(* Logix 5000 project; controller segFORCE_EIP_V1_0 vendor 1 type 14 code 87 rev 20.12; software revision 20.04 *)

TASK MainTask (continuous, watchdog 500 ms) : MainProgram

MODULES
   Controller : vendor 1 type 14 code 87 (CompactLogixL23E_QB1_Controller 0, rev 20.12)
      LocalENB : vendor 1 type 12 code 190 (CompactLogixL23E_QB1_Ethernet 1, Ethernet 192.168.10.88, rev 20.11)
         segFORCE : vendor 1219 type 43 code 100 (Ethernet 192.168.10.82, rev 1.1, StandardDataDriven RPI 2 ms)
      Local : CompactBus (CompactVirtualAdapter 3, rev 20.11)
         Discrete_Inputs : vendor 1 type 7 code 320 (Compact 1, rev 3.1, Input RPI 20 ms)
         Discrete_Outputs : vendor 1 type 7 code 322 (Compact 2, rev 3.1, Output RPI 20 ms)
END_MODULES

TYPE Segment_Status :
STRUCT
   Speed_pulse_status : BOOL;
   Exists : BOOL;
   Group_number : INT;
END_STRUCT
END_TYPE

VAR_GLOBAL   (* controller tags *)
   Group_Mode : DINT;
   msg_Group : MESSAGE;
        MessageParameters(ServiceCode := 16#0010, LocalElement := Group_Mode, ...)
   Status_of_Segments : Segment_Status[50]; {access Read Only}
   Trigger_Group_Write : DINT;
END_VAR

PROGRAM MainProgram   (* main routine MainRoutine *)
VAR
   TempGroupNum : INT;
   TempSegStatus : Segment_Status;
   TempStatusPos : INT;
END_VAR

ROUTINE MainRoutine   (* ladder *)
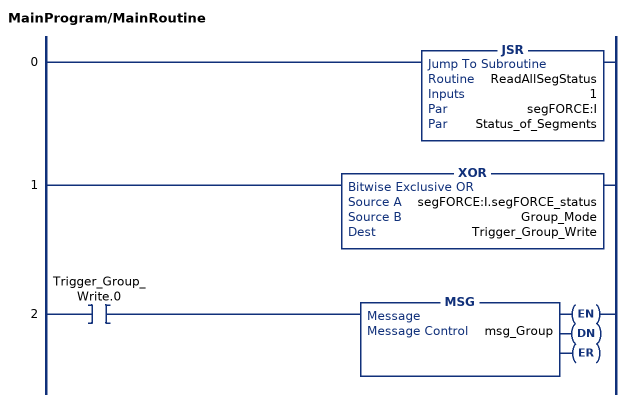
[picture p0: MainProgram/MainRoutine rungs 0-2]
   0: JSR(ReadAllSegStatus,1,segFORCE:I,Status_of_Segments);
   1: XOR(segFORCE:I.segFORCE_status,Group_Mode,Trigger_Group_Write);
   2: XIC(Trigger_Group_Write.0)MSG(msg_Group);
END_ROUTINE

ROUTINE ReadAllSegStatus   (* ladder *)
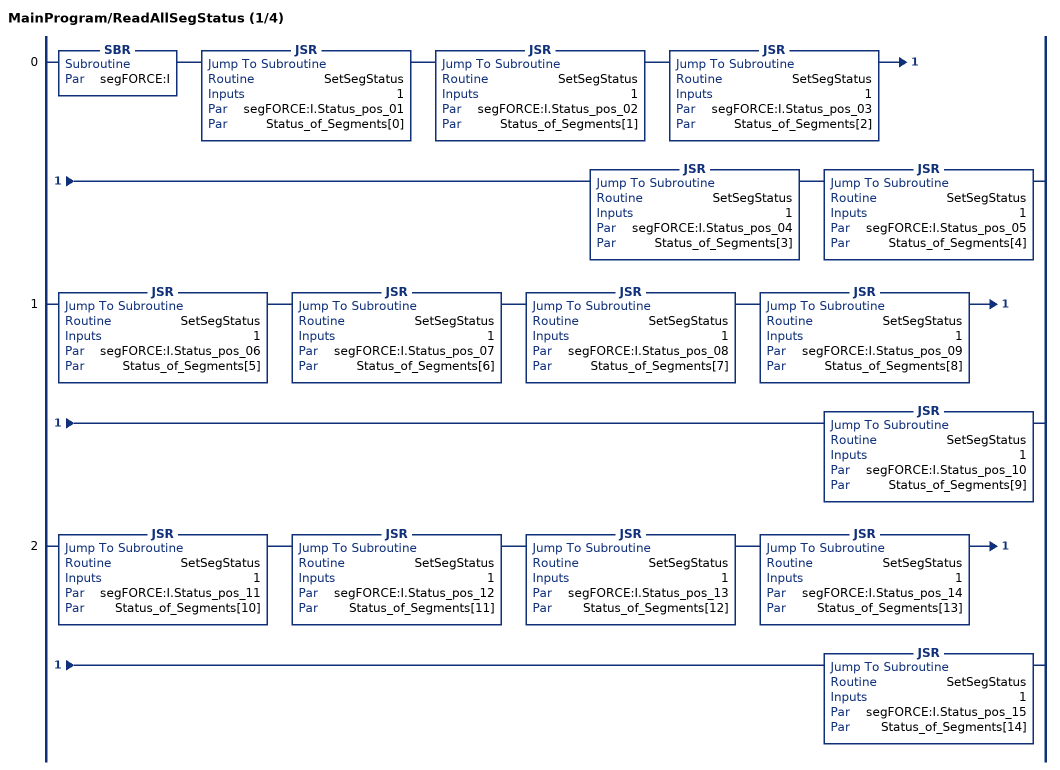
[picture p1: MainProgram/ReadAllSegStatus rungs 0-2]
   0: SBR(segFORCE:I)JSR(SetSegStatus,1,segFORCE:I.Status_pos_01,Status_of_Segments[0])JSR(SetSegStatus,1,segFORCE:I.Status_pos_02,Status_of_Segments[1])JSR(SetSegStatus,1,segFORCE:I.Status_pos_03,Status_of_Segments[2])JSR(SetSegStatus,1,segFORCE:I.Status_pos_04,Status_of_Segments[3])JSR(SetSegStatus,1,segFORCE:I.Status_pos_05,Status_of_Segments[4]);
   1: JSR(SetSegStatus,1,segFORCE:I.Status_pos_06,Status_of_Segments[5])JSR(SetSegStatus,1,segFORCE:I.Status_pos_07,Status_of_Segments[6])JSR(SetSegStatus,1,segFORCE:I.Status_pos_08,Status_of_Segments[7])JSR(SetSegStatus,1,segFORCE:I.Status_pos_09,Status_of_Segments[8])JSR(SetSegStatus,1,segFORCE:I.Status_pos_10,Status_of_Segments[9]);
   2: JSR(SetSegStatus,1,segFORCE:I.Status_pos_11,Status_of_Segments[10])JSR(SetSegStatus,1,segFORCE:I.Status_pos_12,Status_of_Segments[11])JSR(SetSegStatus,1,segFORCE:I.Status_pos_13,Status_of_Segments[12])JSR(SetSegStatus,1,segFORCE:I.Status_pos_14,Status_of_Segments[13])JSR(SetSegStatus,1,segFORCE:I.Status_pos_15,Status_of_Segments[14]);
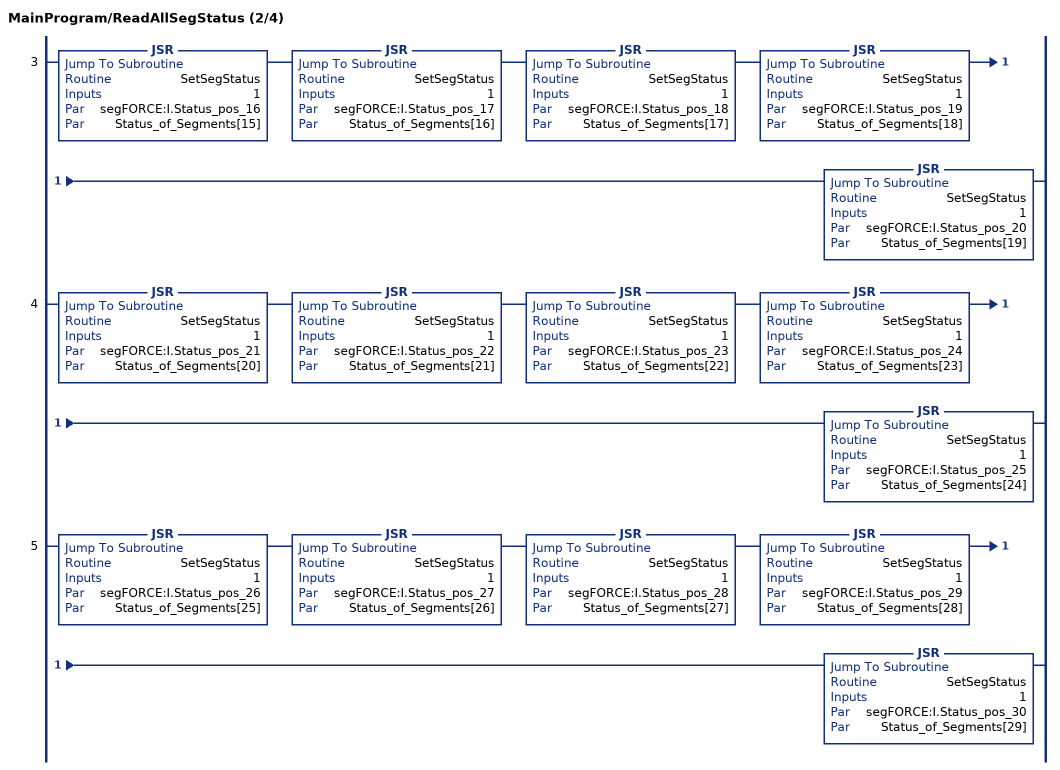
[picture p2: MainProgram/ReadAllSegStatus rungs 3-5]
   3: JSR(SetSegStatus,1,segFORCE:I.Status_pos_16,Status_of_Segments[15])JSR(SetSegStatus,1,segFORCE:I.Status_pos_17,Status_of_Segments[16])JSR(SetSegStatus,1,segFORCE:I.Status_pos_18,Status_of_Segments[17])JSR(SetSegStatus,1,segFORCE:I.Status_pos_19,Status_of_Segments[18])JSR(SetSegStatus,1,segFORCE:I.Status_pos_20,Status_of_Segments[19]);
   4: JSR(SetSegStatus,1,segFORCE:I.Status_pos_21,Status_of_Segments[20])JSR(SetSegStatus,1,segFORCE:I.Status_pos_22,Status_of_Segments[21])JSR(SetSegStatus,1,segFORCE:I.Status_pos_23,Status_of_Segments[22])JSR(SetSegStatus,1,segFORCE:I.Status_pos_24,Status_of_Segments[23])JSR(SetSegStatus,1,segFORCE:I.Status_pos_25,Status_of_Segments[24]);
   5: JSR(SetSegStatus,1,segFORCE:I.Status_pos_26,Status_of_Segments[25])JSR(SetSegStatus,1,segFORCE:I.Status_pos_27,Status_of_Segments[26])JSR(SetSegStatus,1,segFORCE:I.Status_pos_28,Status_of_Segments[27])JSR(SetSegStatus,1,segFORCE:I.Status_pos_29,Status_of_Segments[28])JSR(SetSegStatus,1,segFORCE:I.Status_pos_30,Status_of_Segments[29]);
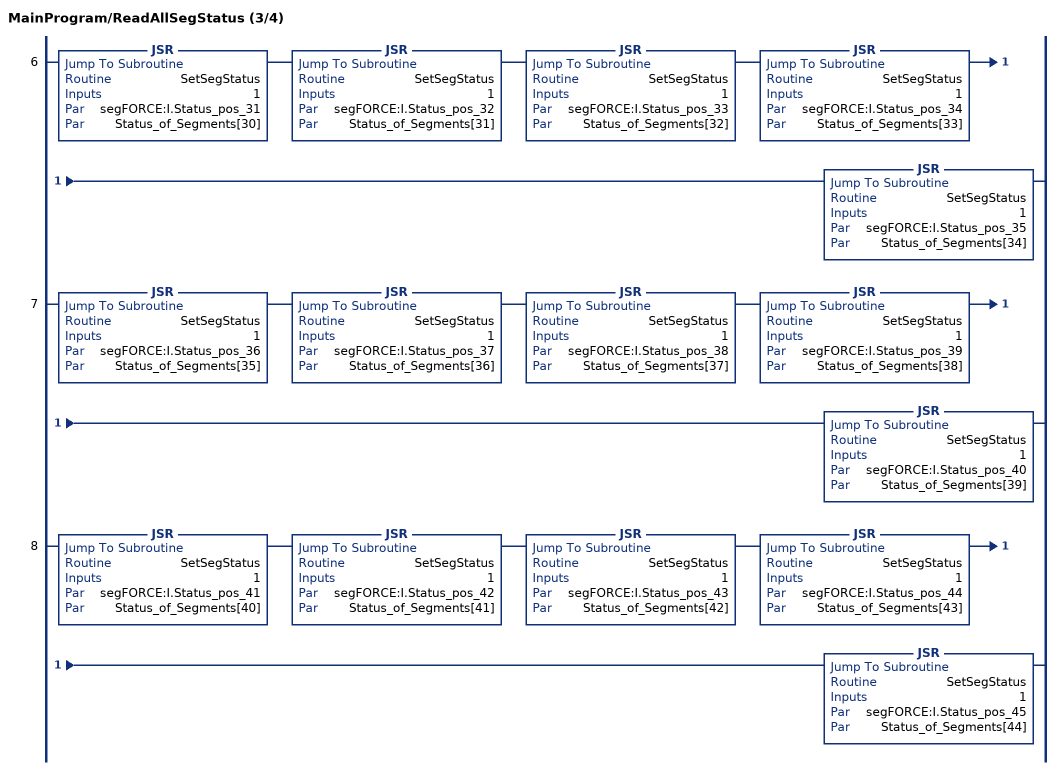
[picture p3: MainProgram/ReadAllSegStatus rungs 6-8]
   6: JSR(SetSegStatus,1,segFORCE:I.Status_pos_31,Status_of_Segments[30])JSR(SetSegStatus,1,segFORCE:I.Status_pos_32,Status_of_Segments[31])JSR(SetSegStatus,1,segFORCE:I.Status_pos_33,Status_of_Segments[32])JSR(SetSegStatus,1,segFORCE:I.Status_pos_34,Status_of_Segments[33])JSR(SetSegStatus,1,segFORCE:I.Status_pos_35,Status_of_Segments[34]);
   7: JSR(SetSegStatus,1,segFORCE:I.Status_pos_36,Status_of_Segments[35])JSR(SetSegStatus,1,segFORCE:I.Status_pos_37,Status_of_Segments[36])JSR(SetSegStatus,1,segFORCE:I.Status_pos_38,Status_of_Segments[37])JSR(SetSegStatus,1,segFORCE:I.Status_pos_39,Status_of_Segments[38])JSR(SetSegStatus,1,segFORCE:I.Status_pos_40,Status_of_Segments[39]);
   8: JSR(SetSegStatus,1,segFORCE:I.Status_pos_41,Status_of_Segments[40])JSR(SetSegStatus,1,segFORCE:I.Status_pos_42,Status_of_Segments[41])JSR(SetSegStatus,1,segFORCE:I.Status_pos_43,Status_of_Segments[42])JSR(SetSegStatus,1,segFORCE:I.Status_pos_44,Status_of_Segments[43])JSR(SetSegStatus,1,segFORCE:I.Status_pos_45,Status_of_Segments[44]);
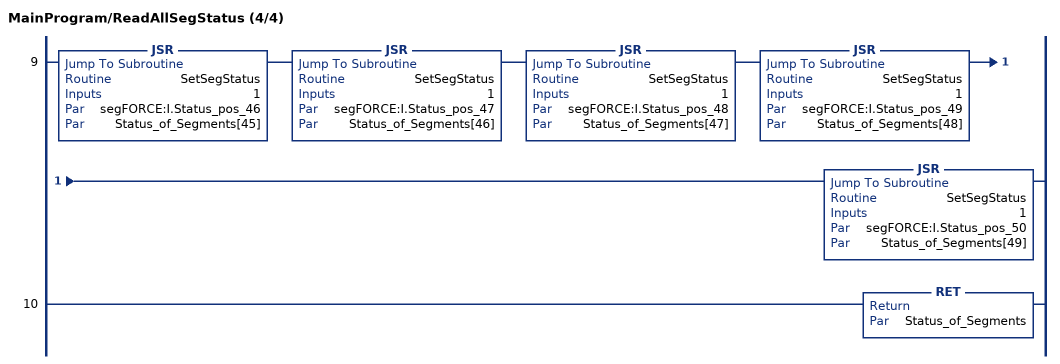
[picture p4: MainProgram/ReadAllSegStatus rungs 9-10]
   9: JSR(SetSegStatus,1,segFORCE:I.Status_pos_46,Status_of_Segments[45])JSR(SetSegStatus,1,segFORCE:I.Status_pos_47,Status_of_Segments[46])JSR(SetSegStatus,1,segFORCE:I.Status_pos_48,Status_of_Segments[47])JSR(SetSegStatus,1,segFORCE:I.Status_pos_49,Status_of_Segments[48])JSR(SetSegStatus,1,segFORCE:I.Status_pos_50,Status_of_Segments[49]);
   10: RET(Status_of_Segments);
END_ROUTINE

ROUTINE SetSegStatus   (* ladder *)
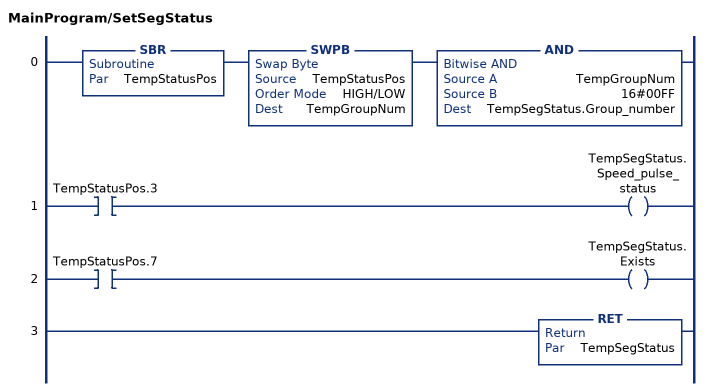
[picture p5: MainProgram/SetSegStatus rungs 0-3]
   0: SBR(TempStatusPos)SWPB(TempStatusPos,HIGH/LOW,TempGroupNum)AND(TempGroupNum,16#00FF,TempSegStatus.Group_number);
   1: XIC(TempStatusPos.3)OTE(TempSegStatus.Speed_pulse_status);
   2: XIC(TempStatusPos.7)OTE(TempSegStatus.Exists);
   3: RET(TempSegStatus);
END_ROUTINE
END_PROGRAM
